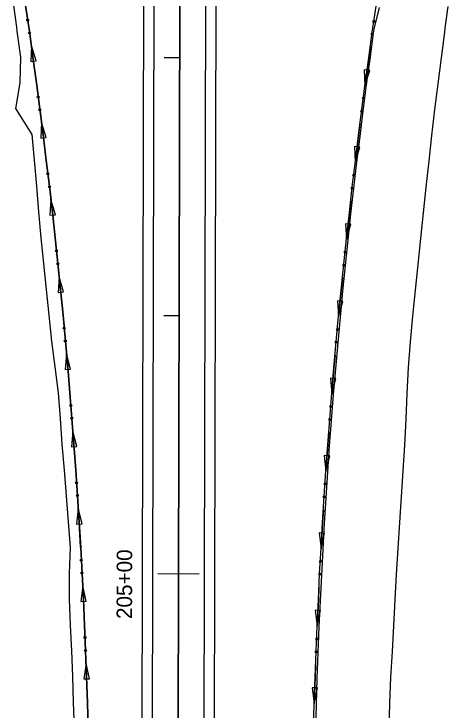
# Model space of a CAD drawing. Extents: x 1611108 to 1749517, y 619561 to 797725.
# Drawn here: x 1717548.2 to 1717716.5, y 765685.2 to 765954.9 of the extents above; entities that cross this region are included whole.
import ezdxf

# ---------------------------------------------------------------- set-up
doc = ezdxf.new("R2010")
doc.units = 0
for name, color, linetype in [('Level 8', 7, 'Continuous'), ('R_Ditch', 7, 'Continuous'), ('R_Horz Alg', 7, 'Continuous'), ('R_Horz Alg Stationing_Side Road', 7, 'Continuous'), ('R_Proposed Const Limits', 7, 'Continuous'), ('R_Proposed Road', 7, 'Continuous'), ('R_Special Ditch', 7, 'Continuous')]:
    doc.layers.add(name, color=color, linetype=linetype)

msp = doc.modelspace()

# ---------------------------------------------------------------- linework, layer by layer
at = {"layer": 'Level 8'}
msp.add_line((1717616.46, 767638.01), (1717610.87, 765238.01), dxfattribs=at)
at = {"layer": 'R_Ditch'}
for p, q in [((1717686.11, 765932.95), (1717684.01, 765933.24)), ((1717684.01, 765933.24), (1717684.25, 765927.15)), ((1717684.25, 765927.15), (1717686.11, 765932.95)), ((1717682.26, 765903.18), (1717680.15, 765903.44)), ((1717680.15, 765903.44), (1717680.47, 765897.35)), ((1717680.47, 765897.35), (1717682.26, 765903.18)), ((1717678.78, 765873.36), (1717676.67, 765873.59)), ((1717676.67, 765873.59), (1717677.07, 765867.51)), ((1717677.07, 765867.51), (1717678.78, 765873.36)), ((1717675.67, 765843.49), (1717673.57, 765843.7)), ((1717673.57, 765843.7), (1717674.04, 765837.62)), ((1717674.04, 765837.62), (1717675.67, 765843.49)), ((1717672.95, 765813.59), (1717670.84, 765813.77)), ((1717670.84, 765813.77), (1717671.39, 765807.7)), ((1717671.39, 765807.7), (1717672.95, 765813.59)), ((1717670.6, 765783.66), (1717668.49, 765783.81)), ((1717668.49, 765783.81), (1717669.12, 765777.75)), ((1717669.12, 765777.75), (1717670.6, 765783.66)), ((1717668.64, 765753.7), (1717666.53, 765753.82)), ((1717666.53, 765753.82), (1717667.23, 765747.77)), ((1717667.23, 765747.77), (1717668.64, 765753.7)), ((1717667.06, 765723.72), (1717664.95, 765723.81)), ((1717664.95, 765723.81), (1717665.73, 765717.77)), ((1717665.73, 765717.77), (1717667.06, 765723.72)), ((1717665.87, 765693.72), (1717663.75, 765693.79)), ((1717663.75, 765693.79), (1717664.61, 765687.75)), ((1717664.61, 765687.75), (1717665.87, 765693.72))]:
    msp.add_line(p, q, dxfattribs=at)
for points in [[(1717577, 765678.09), (1717576.71, 765688.09), (1717576.38, 765698.09), (1717576.01, 765708.1), (1717575.59, 765718.1), (1717575.13, 765728.1), (1717574.63, 765738.1), (1717574.08, 765748.1), (1717573.49, 765758.1), (1717572.86, 765768.1), (1717572.19, 765778.1), (1717571.47, 765788.11), (1717570.71, 765798.11), (1717569.91, 765808.11), (1717569.07, 765818.11), (1717568.18, 765828.11), (1717567.25, 765838.12), (1717566.27, 765848.12), (1717565.26, 765858.12), (1717564.2, 765868.12), (1717563.1, 765878.13), (1717561.95, 765888.13), (1717560.77, 765898.13), (1717559.54, 765908.13), (1717558.27, 765918.14), (1717556.95, 765928.14), (1717555.59, 765938.14), (1717554.19, 765948.15), (1717553.97, 765949.72), (1717552.75, 765958.15)], [(1717577, 765678.09), (1717576.71, 765688.09), (1717576.38, 765698.09), (1717576.01, 765708.1), (1717575.59, 765718.1), (1717575.13, 765728.1), (1717574.63, 765738.1), (1717574.08, 765748.1), (1717573.49, 765758.1), (1717572.86, 765768.1), (1717572.19, 765778.1), (1717571.47, 765788.11), (1717570.71, 765798.11), (1717569.91, 765808.11), (1717569.07, 765818.11), (1717568.18, 765828.11), (1717567.25, 765838.12), (1717566.27, 765848.12), (1717565.26, 765858.12), (1717564.2, 765868.12), (1717563.1, 765878.13), (1717561.95, 765888.13), (1717560.77, 765898.13), (1717559.54, 765908.13), (1717558.27, 765918.14), (1717556.95, 765928.14), (1717555.59, 765938.14), (1717554.19, 765948.15), (1717553.97, 765949.72), (1717552.75, 765958.15)], [(1717577, 765678.09), (1717576.71, 765688.09), (1717576.38, 765698.09), (1717576.01, 765708.1), (1717575.59, 765718.1), (1717575.13, 765728.1), (1717574.63, 765738.1), (1717574.08, 765748.1), (1717573.49, 765758.1), (1717572.86, 765768.1), (1717572.19, 765778.1), (1717571.47, 765788.11), (1717570.71, 765798.11), (1717569.91, 765808.11), (1717569.07, 765818.11), (1717568.18, 765828.11), (1717567.25, 765838.12), (1717566.27, 765848.12), (1717565.26, 765858.12), (1717564.2, 765868.12), (1717563.1, 765878.13), (1717561.95, 765888.13), (1717560.77, 765898.13), (1717559.54, 765908.13), (1717558.27, 765918.14), (1717556.95, 765928.14), (1717555.59, 765938.14), (1717554.19, 765948.15), (1717553.97, 765949.72), (1717552.75, 765958.15)], [(1717664.33, 765677.89), (1717664.62, 765687.89), (1717664.95, 765697.89), (1717665.32, 765707.89), (1717665.74, 765717.89), (1717666.19, 765727.89), (1717666.7, 765737.88), (1717667.24, 765747.88), (1717667.83, 765757.88), (1717668.46, 765767.88), (1717669.13, 765777.88), (1717669.84, 765787.88), (1717670.6, 765797.88), (1717671.4, 765807.87), (1717672.25, 765817.87), (1717673.13, 765827.87), (1717674.06, 765837.87), (1717675.03, 765847.87), (1717676.05, 765857.86), (1717677.11, 765867.86), (1717678.21, 765877.86), (1717679.35, 765887.86), (1717680.53, 765897.85), (1717681.76, 765907.85), (1717683.03, 765917.85), (1717684.35, 765927.84), (1717685.7, 765937.84), (1717687.1, 765947.84), (1717687.33, 765949.41), (1717688.55, 765957.83)], [(1717665.18, 765677.41), (1717665.46, 765687.41), (1717665.78, 765697.41), (1717666.14, 765707.41), (1717666.54, 765717.41), (1717666.99, 765727.41), (1717667.48, 765737.41), (1717668.01, 765747.41), (1717668.58, 765757.41), (1717669.2, 765767.4), (1717669.86, 765777.4), (1717670.57, 765787.4), (1717671.31, 765797.4), (1717672.1, 765807.4), (1717672.93, 765817.4), (1717673.81, 765827.39), (1717674.72, 765837.39), (1717675.68, 765847.39), (1717676.69, 765857.39), (1717677.73, 765867.38), (1717678.82, 765877.38), (1717679.95, 765887.38), (1717681.12, 765897.38), (1717682.34, 765907.37), (1717683.6, 765917.37), (1717684.9, 765927.37), (1717686.24, 765937.37), (1717687.63, 765947.36), (1717687.85, 765948.93), (1717689.95, 765957.36)], [(1717686.29, 765942.01), (1717685.7, 765937.84), (1717684.35, 765927.84), (1717684.26, 765927.15)], [(1717686.29, 765942.05), (1717686.29, 765942.01)], [(1717682.32, 765912.24), (1717681.76, 765907.85), (1717680.53, 765897.85), (1717680.48, 765897.35)], [(1717682.33, 765912.27), (1717682.32, 765912.24)], [(1717678.73, 765882.42), (1717678.21, 765877.86), (1717677.11, 765867.86), (1717677.07, 765867.51)], [(1717678.73, 765882.45), (1717678.73, 765882.42)], [(1717675.51, 765852.55), (1717675.03, 765847.87), (1717674.06, 765837.87), (1717674.04, 765837.62)], [(1717675.51, 765852.59), (1717675.51, 765852.55)], [(1717672.67, 765822.65), (1717672.25, 765817.87), (1717671.4, 765807.87), (1717671.39, 765807.7)], [(1717672.67, 765822.68), (1717672.67, 765822.65)], [(1717670.21, 765792.71), (1717669.84, 765787.88), (1717669.13, 765777.88), (1717669.12, 765777.75)], [(1717670.21, 765792.75), (1717670.21, 765792.71)], [(1717668.13, 765762.74), (1717667.83, 765757.88), (1717667.24, 765747.88), (1717667.23, 765747.77)], [(1717668.14, 765762.78), (1717668.13, 765762.74)], [(1717666.44, 765732.75), (1717666.19, 765727.89), (1717665.74, 765717.89), (1717665.73, 765717.77)], [(1717666.44, 765732.79), (1717666.44, 765732.75)], [(1717665.13, 765702.75), (1717664.95, 765697.89), (1717664.62, 765687.89), (1717664.61, 765687.75)], [(1717665.13, 765702.78), (1717665.13, 765702.75)]]:
    msp.add_lwpolyline(points, dxfattribs=at)
for centre in [(1717687.73, 765951.94), (1717687.02, 765946.98), (1717683.64, 765922.18), (1717682.99, 765917.21), (1717679.92, 765892.38), (1717679.33, 765887.4), (1717676.58, 765862.53), (1717676.05, 765857.54), (1717673.61, 765832.63), (1717673.15, 765827.65), (1717671.03, 765802.71), (1717670.63, 765797.72), (1717668.82, 765772.75), (1717668.49, 765767.75), (1717667, 765742.77), (1717666.73, 765737.77), (1717665.56, 765712.77), (1717665.35, 765707.76)]:
    msp.add_circle(centre, 0.375, dxfattribs=at)
at = {"layer": 'R_Horz Alg'}
msp.add_line((1717610.87, 765238.01), (1717616.46, 767638.01), dxfattribs=at)
at = {"layer": 'R_Horz Alg Stationing_Side Road'}
for points in [[(1717606.5, 765938.03), (1717612.5, 765938.01)], [(1717606.27, 765838.03), (1717612.27, 765838.01)], [(1717604.03, 765738.03), (1717620.03, 765737.99)]]:
    msp.add_lwpolyline(points, dxfattribs=at)
at = {"layer": 'R_Proposed Const Limits'}
for points in [[(1717571.63, 765678.11), (1717571.32, 765688.11), (1717570.98, 765698.11), (1717570.61, 765708.11), (1717570.18, 765718.11), (1717569.71, 765728.11), (1717569.78, 765738.11), (1717570.14, 765748.11), (1717569.34, 765758.11), (1717568.61, 765768.11), (1717567.85, 765778.12), (1717566.96, 765788.12), (1717566.26, 765798.12), (1717565.55, 765808.12), (1717564.23, 765818.12), (1717562.93, 765828.13), (1717561.9, 765838.13), (1717560.86, 765848.13), (1717559.76, 765858.13), (1717558.8, 765868.14), (1717557.89, 765878.14), (1717557.05, 765888.14), (1717556.16, 765898.14), (1717555.27, 765908.14), (1717548.91, 765918.16), (1717550.62, 765928.16), (1717550.84, 765938.16), (1717549.53, 765948.16), (1717549.32, 765949.73), (1717548.21, 765958.16)], [(1717693.67, 765677.82), (1717693.9, 765687.82), (1717694.31, 765697.82), (1717694.87, 765707.82), (1717695.42, 765717.82), (1717695.93, 765727.82), (1717696.49, 765737.82), (1717697.1, 765747.81), (1717697.77, 765757.81), (1717698.4, 765767.81), (1717699.06, 765777.81), (1717699.75, 765787.81), (1717700.24, 765797.81), (1717700.64, 765807.81), (1717701.08, 765817.81), (1717701.93, 765827.8), (1717702.86, 765837.8), (1717703.84, 765847.8), (1717704.84, 765857.8), (1717705.9, 765867.79), (1717706.97, 765877.79), (1717708, 765887.79), (1717709.08, 765897.79), (1717710.22, 765907.78), (1717711.4, 765917.78), (1717712.59, 765927.78), (1717713.86, 765937.78), (1717715.15, 765947.77), (1717715.37, 765949.34), (1717716.47, 765957.77)]]:
    msp.add_lwpolyline(points, dxfattribs=at)
at = {"layer": 'R_Proposed Road'}
for p, q in [((1717597.57, 765538.05), (1717601.76, 767338.04)), ((1717601.57, 765538.04), (1717605.76, 767338.03)), ((1717621.57, 765537.99), (1717625.76, 767337.98)), ((1717625.57, 765537.98), (1717629.76, 767337.98))]:
    msp.add_line(p, q, dxfattribs=at)
at = {"layer": 'R_Special Ditch'}
for p, q in [((1717554.98, 765942.52), (1717554.76, 765936.43)), ((1717556.86, 765936.72), (1717554.98, 765942.52)), ((1717554.76, 765936.43), (1717556.86, 765936.72)), ((1717558.95, 765912.74), (1717558.66, 765906.66)), ((1717560.76, 765906.92), (1717558.95, 765912.74)), ((1717558.66, 765906.66), (1717560.76, 765906.92)), ((1717562.55, 765882.92), (1717562.18, 765876.84)), ((1717564.28, 765877.08), (1717562.55, 765882.92)), ((1717562.18, 765876.84), (1717564.28, 765877.08)), ((1717565.77, 765853.06), (1717565.33, 765846.98)), ((1717567.43, 765847.19), (1717565.77, 765853.06)), ((1717565.33, 765846.98), (1717567.43, 765847.19)), ((1717568.62, 765823.15), (1717568.09, 765817.08)), ((1717570.2, 765817.27), (1717568.62, 765823.15)), ((1717568.09, 765817.08), (1717570.2, 765817.27)), ((1717571.08, 765793.22), (1717570.48, 765787.15)), ((1717572.59, 765787.31), (1717571.08, 765793.22)), ((1717570.48, 765787.15), (1717572.59, 765787.31)), ((1717573.17, 765763.25), (1717572.49, 765757.2)), ((1717574.6, 765757.33), (1717573.17, 765763.25)), ((1717572.49, 765757.2), (1717574.6, 765757.33)), ((1717574.87, 765733.26), (1717574.12, 765727.22)), ((1717576.23, 765727.32), (1717574.87, 765733.26)), ((1717574.12, 765727.22), (1717576.23, 765727.32)), ((1717576.19, 765703.25), (1717575.36, 765697.22)), ((1717577.47, 765697.3), (1717576.19, 765703.25)), ((1717575.36, 765697.22), (1717577.47, 765697.3))]:
    msp.add_line(p, q, dxfattribs=at)
for points in [[(1717552.75, 765958.15), (1717553.97, 765949.72), (1717554.19, 765948.15), (1717555.59, 765938.14), (1717556.95, 765928.14), (1717558.27, 765918.14), (1717559.54, 765908.13), (1717560.77, 765898.13), (1717561.95, 765888.13), (1717563.1, 765878.13), (1717564.2, 765868.12), (1717565.26, 765858.12), (1717566.27, 765848.12), (1717567.25, 765838.12), (1717568.18, 765828.11), (1717569.07, 765818.11), (1717569.91, 765808.11), (1717570.71, 765798.11), (1717571.47, 765788.11), (1717572.19, 765778.1), (1717572.86, 765768.1), (1717573.49, 765758.1), (1717574.08, 765748.1), (1717574.63, 765738.1), (1717575.13, 765728.1), (1717575.59, 765718.1), (1717576.01, 765708.1), (1717576.38, 765698.09), (1717576.71, 765688.09), (1717577, 765678.09)], [(1717557.01, 765927.66), (1717556.95, 765928.14), (1717555.59, 765938.14), (1717554.98, 765942.52)], [(1717557.02, 765927.62), (1717557.01, 765927.65)], [(1717560.8, 765897.86), (1717560.77, 765898.13), (1717559.54, 765908.13), (1717558.95, 765912.74)], [(1717560.8, 765897.82), (1717560.8, 765897.86)], [(1717564.21, 765868.01), (1717564.2, 765868.12), (1717563.1, 765878.13), (1717562.55, 765882.92)], [(1717564.22, 765867.98), (1717564.21, 765868.01)], [(1717567.25, 765838.13), (1717566.27, 765848.12), (1717565.77, 765853.06)], [(1717567.25, 765838.09), (1717567.25, 765838.12), (1717567.25, 765838.13)], [(1717569.9, 765808.21), (1717569.07, 765818.11), (1717568.62, 765823.15)], [(1717569.91, 765808.17), (1717569.9, 765808.21)], [(1717572.18, 765778.26), (1717571.47, 765788.11), (1717571.08, 765793.22)], [(1717572.18, 765778.22), (1717572.18, 765778.26)], [(1717574.07, 765748.28), (1717573.49, 765758.1), (1717573.17, 765763.25)], [(1717574.07, 765748.24), (1717574.07, 765748.28)], [(1717575.58, 765718.28), (1717575.13, 765728.1), (1717574.87, 765733.26)], [(1717575.58, 765718.24), (1717575.58, 765718.28)], [(1717576.71, 765688.26), (1717576.38, 765698.09), (1717576.19, 765703.25)], [(1717576.71, 765688.23), (1717576.71, 765688.26)]]:
    msp.add_lwpolyline(points, dxfattribs=at)
for centre in [(1717553.54, 765952.43), (1717554.25, 765947.47), (1717557.63, 765922.67), (1717558.28, 765917.7), (1717561.36, 765892.87), (1717561.95, 765887.89), (1717564.7, 765863.02), (1717565.23, 765858.03), (1717567.68, 765833.13), (1717568.14, 765828.14), (1717570.27, 765803.2), (1717570.67, 765798.21), (1717572.48, 765773.24), (1717572.82, 765768.25), (1717574.31, 765743.26), (1717574.58, 765738.26), (1717575.76, 765713.26), (1717575.96, 765708.25)]:
    msp.add_circle(centre, 0.375, dxfattribs=at)

# ---------------------------------------------------------------- texts
at = {"layer": 'R_Horz Alg Stationing_Side Road'}
msp.add_text('205+00', height=6, rotation=89.8667, dxfattribs=at).set_placement((1717593.99, 765720.41))

doc.saveas('drawing.dxf')
